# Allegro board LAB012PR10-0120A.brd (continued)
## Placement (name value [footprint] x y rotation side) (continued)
PC2  100P_0402_50V8J  [C_0402]  17.33 116.84 270 bottom
PC3  1000P_0402_50V7K  [C_0402]  17.33 113.77 90 bottom
PC4  100P_0402_50V8J  [C_0402]  16.31 113.77 90 bottom
PC5  0.1U_0402_25V6  [C_0402]  36.56 108.13 0 top
PC7  0.01U_0402_25V7K  [C_0402]  20.76 30.46 90 top
PC8  1000P_0402_50V7K  [C_0402]  19.49 30.46 90 top
PC13  .1U_0402_16V7K  [C_0402]  43.16 116.77 0 top
PC14  .1U_0402_16V7K  [C_0402]  81.39 51.44 0 bottom
PC15  0.01U_0402_25V7K  [C_0402]  84.64 49.34 270 bottom
PC16  .1U_0402_16V7K  [C_0402]  36.51 113.67 270 top
PC17  .1U_0402_16V7K  [C_0402]  38.36 117.28 180 top
PC100  4.7U_0603_6.3V6K  [C_0603]  75.22 9.29 180 top
PC101  220U_6.3V_M  [C_MP6VLPS220MC4R2]  70.65 27.86 90 bottom
PC102  100P_0402_50V8J  [C_0402]  76.35 20.11 180 top
PC103  680P_0603_50V8J  [C_0603]  67.67 25 270 top
PC104  0.22U_0603_25V7K  [C_0603]  73.15 21.52 90 top
PC105  1U_0603_25V6K  [C_0603]  70.33 18.83 270 bottom
PC106  4.7U_0603_10V6K  [C_0603]  68.23 17.86 270 bottom
PC107  220U_6.3V_M  [C_MP6VLPS220MC4R2]  71 8.36 270 bottom
PC108  100P_0402_50V8J  [C_0402]  75.42 16.82 0 bottom
PC109  4.7U_0603_10V6K  [C_0603]  75.49 18.1 0 top
PC110  0.22U_0603_25V7K  [C_0603]  71.77 12.98 90 top
PC111  680P_0603_50V8J  [C_0603]  67.49 13.83 90 top
PC112  10U_0805_25V6K  [C_0805]  63.04 19.41 0 bottom
PC113  0.1U_0402_25V7K  [C_0402]  62.85 18.44 0 top
PC114  2200P_0402_50V7K  [C_0402]  62.85 19.33 0 top
PC115  10U_0805_25V6K  [C_0805]  62.32 20.63 0 top
PC116  2200P_0402_50V7K  [C_0402]  62.85 18.11 0 bottom
PC117  0.1U_0402_25V7K  [C_0402]  62.85 17.25 0 bottom
PC200  0.1U_0603_25V7K  [C_0603]  88.89 13.01 180 bottom
PC201  2200P_0402_50V7K  [C_0402]  83.11 16.49 90 bottom
PC202  0.1U_0402_10V7K  [C_0402]  81.03 10.6 180 bottom
PC203  0.1U_0402_10V7K  [C_0402]  81.03 8.82 180 bottom
PC204  1U_0603_10V6K  [C_0603]  84.13 15.99 270 top
PC205  10U_0805_6.3V6K  [C_0805]  88.7 9.42 270 bottom
PC206  10U_0805_25V6K  [C_0805]  86.29 16.22 90 bottom
PC207  680P_0402_50V7K  [C_0402]  89.29 21.77 180 bottom
PC208  0.1U_0402_25V6  [C_0402]  82.23 16.49 90 bottom
PC209  1U_0603_10V6K  [C_0603]  82.86 14.6 90 top
PC210  0.033U_0402_16V7K  [C_0402]  84.13 8.26 270 bottom
PC211  10U_0805_6.3V6K  [C_0805]  87.27 7.93 180 bottom
PC212  10U_0805_25V6K  [C_0805]  84.51 16.22 90 bottom
PC213  330U_2.5V_M  [C_MP6VU330MC6]  99.37 10.98 180 bottom
PC214  220P_0402_25V8J  [C_0402]  81.9 7.42 0 top
PC300  0.22U_0402_10V6K  [C_0402]  182.99 44.89 0 bottom
PC301  680P_0603_50V7K  [C_0603]  173.92 47.24 90 bottom
PC302  0.1U_0603_25V7K  [C_0603]  183.76 53.01 180 bottom
PC303  2200P_0402_50V7K  [C_0402]  176.08 52.96 270 bottom
PC304  0.1U_0402_25V6  [C_0402]  175.19 52.96 270 bottom
PC305  10U_0805_25V6K  [C_0805]  178.49 52.93 90 bottom
PC306  10U_0805_25V6K  [C_0805]  173.79 52.98 270 bottom
PC307  330P_0402_50V7K  [C_0402]  183.88 48.44 0 bottom
PC308  47U_0805_6.3V6M  [C_0805]  182.43 38.96 90 top
PC309  47U_0805_6.3V6M  [C_0805]  180.52 38.96 90 top
PC310  22U_0805_6.3VAM  [C_0805]  176.97 38.96 90 top
PC311  22U_0805_6.3VAM  [C_0805]  178.75 38.96 90 top
PC312  4.7U_0603_6.3V6K  [C_0603]  182.37 50.47 0 bottom
PC313  4.7U_0603_6.3V6K  [C_0603]  179.83 53.01 0 bottom
PC400  1U_0402_6.3V6K  [C_0402]  210.11 8.63 0 top
PC401  4.7U_0603_10V6K  [C_0603]  208.71 6.85 0 top
PC402  0.1U_0402_16V7K  [C_0402]  210.11 11.74 0 top
PC403  0.01U_0402_25V7K  [C_0402]  200.84 11.93 0 top
PC404  22U_0805_6.3V6M  [C_0805]  201.3 8.28 90 top
PC500  1000P_0402_50V7K  [C_0402]  66.94 111.18 180 bottom
PC510  47P_0402_50V8J  [C_0402]  66.02 109.15 0 bottom
PC515  100U_25V_M  [C_EEEFZ1E101P]  66.86 114.86 90 bottom
PC516  100U_25V_M  [C_EEEFZ1E101P]  73.97 114.86 90 bottom
PC517  10U_0805_25V6K  [C_0805]  78.2 112.32 0 top
PC518  10U_0805_25V6K  [C_0805]  77.69 114.74 0 top
PC519  0.1U_0402_25V7K  [C_0402]  78.47 110.93 0 top
PC520  680P_0402_50V7K  [C_0402]  86.54 119.74 90 bottom
PC521  2200P_0402_25V7K  [C_0402]  78.47 110.93 0 bottom
PC522  82P_0402_50V8J  [C_0402]  68.38 105.29 270 top
PC523  4700P_0402_50V7K  [C_0402]  70.41 106.43 270 top
PC524  10U_0805_25V6K  [C_0805]  78.2 112.32 0 bottom
PC525  0.22U_0603_16V7K  [C_0603]  75.18 111.31 180 top
PC526  6800P_0402_25V7K  [C_0402]  66.94 107.12 180 bottom
PC527  330P_0402_50V7K  [C_0402]  67.42 103.43 0 bottom
PC528  0.1U_0603_25V7K  [C_0603]  73.78 109.35 0 bottom
PC529  0.1U_0402_10V6K  [C_0402]  75.49 105.59 180 top
PC530  .047U_0402_16V7K  [C_0402]  72.5 106.48 0 top
PC531  33P_0402_50V8J  [C_0402]  65.77 105.85 0 bottom
PC532  10U_0805_25V6K  [C_0805]  78.2 109.53 0 bottom
PC541  330P_0402_50V7K  [C_0402]  68.38 107.57 270 bottom
PC545  0.082U_0402_16V7K  [C_0402]  68.31 106.61 0 top
PC546  0.01U_0402_50V7K  [C_0402]  69.27 107.57 270 bottom
PC548  1U_0402_6.3V6K  [C_0402]  61.02 111.64 270 bottom
PC600  22U_0805_6.3VAM  [C_0805]  90.34 29.51 270 bottom
PC601  680P_0402_50V7K  [C_0402]  84.42 25.2 0 bottom
PC602  22U_0805_6.3VAM  [C_0805]  88.63 29.51 270 bottom
PC603  0.1U_0402_16V7K  [C_0402]  88.88 26.67 270 bottom
PC604  68P_0402_50V8J  [C_0402]  90.66 24.51 270 bottom
PC605  22U_0805_6.3VAM  [C_0805]  84.88 22.44 90 bottom
PC701  1000P_0402_50V7K  [C_0402]  46.86 7.28 0 bottom
PC702  0.022U_0402_25V7K  [C_0402]  26.97 40.95 180 bottom
PC703  10U_0805_25V6K  [C_0805]  37.23 33.2 180 top
PC704  10U_0805_25V6K  [C_0805]  37.23 35.11 180 top
PC705  2200P_0402_25V7K  [C_0402]  37.09 31.81 180 top
PC706  0.1U_0402_25V7K  [C_0402]  37.09 30.92 180 top
PC707  0.1U_0402_25V6  [C_0402]  47.94 18.27 90 bottom
PC708  0.1U_0402_25V6  [C_0402]  45.27 18.27 90 bottom
PC709  1U_0603_10V6K  [C_0603]  37.22 17.26 0 bottom
PC710  1U_0603_25V6K  [C_0603]  49.27 17.84 0 bottom
PC711  0.01UF_0402_25V7K  [C_0402]  50.81 14.53 180 bottom
PC712  10U_0805_25V6K  [C_0805]  24.91 16.06 180 bottom
PC713  10U_0805_25V6K  [C_0805]  24.91 17.84 180 bottom
PC714  10U_0805_25V6K  [C_0805]  27.11 29.05 90 top
PC715  680P_0402_50V7K  [C_0402]  41.2 31.35 90 bottom
PC716  10U_0805_25V6K  [C_0805]  24.91 19.61 180 bottom
PC717  0.047U_0402_25V7K  [C_0402]  47 17.33 180 bottom
PC718  10U_0805_25V6K  [C_0805]  30.1 29.1 90 top
PC719  1U_0603_10V6K  [C_0603]  37.24 18.48 0 bottom
PC720  1000P_0402_25V8J  [C_0402]  47.19 8.84 90 bottom
PC721  0.22U_0603_25V7K  [C_0603]  42.35 19.42 270 bottom
PC722  1U_0603_25V6K  [C_0603]  38.93 15.65 180 bottom
PC723  0.47U_0402_6.3V6K  [C_0402]  16.31 35.06 270 top
PC724  1000P_0402_25V8J  [C_0402]  18.9 23.42 0 bottom
PC725  1000P_0402_25V8J  [C_0402]  40.58 11.12 90 bottom
PC726  .1U_0402_16V7K  [C_0402]  44.48 8.87 90 bottom
PC727  220P_0402_50V8J  [C_0402]  49.56 8.77 90 bottom
PC728  2200P_0402_50V7K  [C_0402]  50.79 12.29 180 bottom
PC729  10U_0805_25V6K  [C_0805]  35.82 36.21 270 bottom
PC730  10U_0805_25V6K  [C_0805]  37.6 36.21 270 bottom
PC731  10U_0805_25V6K  [C_0805]  39.38 36.21 270 bottom
PC732  100U_25V_M  [C_EEEFZ1E101P]  46.79 23.42 90 bottom
PC733  5600P_0402_25V7K  [C_0402]  31.51 37.93 90 top
PC734  10U_0805_25V6K  [C_0805]  37.23 37.01 180 top
PC735  10U_0805_25V6K  [C_0805]  14.79 113.38 90 bottom
PC736  10U_0805_25V6K  [C_0805]  32.06 31.7 0 top
PC737  10U_0805_25V6K  [C_0805]  32.06 29.91 0 top
PC738  10U_0805_25V6K  [C_0805]  32.06 28.09 0 top
PC739  10U_0805_25V6K  [C_0805]  32.06 26.28 0 top
PC836  330U_D2_2V_Y  [C_D2]  57.97 63.71 270 top
PC837  330U_D2_2V_Y  [C_D2]  62.67 63.71 270 top
PC838  330U_D2_2V_Y  [C_D2]  67.37 63.71 270 top
PC839  330U_D2_2V_Y  [C_D2]  67.14 68.13 180 top
PC840  2.2U_0402_6.3V6M  [C_0402]  64.98 87.05 270 top
PC841  2.2U_0402_6.3V6M  [C_0402]  61.45 88.35 0 top
PC842  2.2U_0402_6.3V6M  [C_0402]  64.4 89.26 180 top
PC843  2.2U_0402_6.3V6M  [C_0402]  62.74 66.86 180 bottom
PC844  2.2U_0402_6.3V6M  [C_0402]  65.79 67.75 180 bottom
PC845  2.2U_0402_6.3V6M  [C_0402]  65.79 69.52 180 bottom
PC846  2.2U_0402_6.3V6M  [C_0402]  62.74 69.52 180 bottom
PC847  2.2U_0402_6.3V6M  [C_0402]  67.75 67.03 90 bottom
PC848  2.2U_0402_6.3V6M  [C_0402]  66.86 67.03 90 bottom
PC849  2.2U_0402_6.3V6M  [C_0402]  62.74 68.64 180 bottom
PC850  2.2U_0402_6.3V6M  [C_0402]  65.79 68.64 180 bottom
PC851  2.2U_0402_6.3V6M  [C_0402]  67.29 83.24 90 top
PC852  2.2U_0402_6.3V6M  [C_0402]  63.61 82.27 90 top
PC853  10U_0603_6.3V6M  [C_0603]  68.89 66.54 90 bottom
PC854  10U_0603_6.3V6M  [C_0603]  54.46 64.33 180 top
PC855  10U_0603_6.3V6M  [C_0603]  69.02 63.75 90 bottom
PC856  10U_0603_6.3V6M  [C_0603]  70.16 66.54 90 bottom
PC857  10U_0603_6.3V6M  [C_0603]  54.45 65.56 180 top
PC858  10U_0603_6.3V6M  [C_0603]  69.02 62.6 270 bottom
PC859  0.1U_0402_10V7K  [C_0402]  62.74 67.75 180 bottom
PC860  0.1U_0402_10V7K  [C_0402]  65.79 66.86 180 bottom
PC869  2.2U_0402_6.3V6M  [C_0402]  62.74 70.41 180 bottom
PC871  2.2U_0402_6.3V6M  [C_0402]  66.73 88.29 180 top
PC872  2.2U_0402_6.3V6M  [C_0402]  66.88 89.16 90 top
PC901  22U_0805_6.3V6M  [C_0805]  102.71 119.82 0 bottom
PC902  22U_0805_6.3V6M  [C_0805]  140.9 99.15 90 top
PC903  22U_0805_6.3V6M  [C_0805]  111.14 117.28 180 top
PC904  22U_0805_6.3V6M  [C_0805]  127.91 116.13 180 top
PC905  22U_0805_6.3V6M  [C_0805]  102.71 116.39 0 bottom
PC906  22U_0805_6.3V6M  [C_0805]  119.27 113.92 180 top
PC907  22U_0805_6.3V6M  [C_0805]  121.09 99.15 90 top
PC908  22U_0805_6.3V6M  [C_0805]  123.97 116.13 180 top
PC909  22U_0805_6.3V6M  [C_0805]  119.27 117.4 180 top
PC910  22U_0805_6.3V6M  [C_0805]  111.14 113.85 180 top
PC911  22U_0805_6.3V6M  [C_0805]  115.46 117.4 180 top
PC912  22U_0805_6.3V6M  [C_0805]  123.97 112.58 180 top
PC913  22U_0805_6.3V6M  [C_0805]  115.33 113.92 180 top
PC914  2.2U_0402_6.3V6M  [C_0402]  127.53 112.51 180 top
PC915  22U_0805_6.3V6M  [C_0805]  138.61 99.15 90 top
PC916  22U_0805_6.3V6M  [C_0805]  136.07 99.15 90 top
PC917  22U_0805_6.3V6M  [C_0805]  133.53 99.15 90 top
PC918  22U_0805_6.3V6M  [C_0805]  131.12 99.15 90 top
PC919  22U_0805_6.3V6M  [C_0805]  128.45 99.15 90 top
PC920  22U_0805_6.3V6M  [C_0805]  125.91 99.15 90 top
PC921  22U_0805_6.3V6M  [C_0805]  123.37 99.15 90 top
PC922  22U_0805_6.3V6M  [C_0805]  122.99 93.95 90 top
PC923  22U_0805_6.3V6M  [C_0805]  122.99 90.14 90 top
PC924  220U_D2_2.5VY_R9M  [C_D2]  127.79 95.18 0 top
PC1019  0.1U_0402_25V6K  [C_0402]  60.01 32.58 90 top
PC1020  1U_0603_10V6K  [C_0603]  61.21 39.17 180 top
PC1021  1U_0603_10V6K  [C_0603]  63.3 40.38 90 top
PC1022  1000P_0402_50V7K  [C_0402]  58.12 33.43 270 top
PC1023  10U_0805_25V6K  [C_0805]  57.84 45.22 90 top
PC1024  10U_0805_25V6K  [C_0805]  57.84 45.22 90 bottom
PC1025  2200P_0402_50V7K  [C_0402]  59.24 45.65 90 top
PC1026  0.22U_0603_25V7K  [C_0603]  59.49 43.17 270 bottom
PC1027  1000P_0402_50V7K  [C_0402]  57.16 39.55 180 top
PC1028  100P_0402_50V8J  [C_0402]  57.16 38.92 180 bottom
PC1029  680P_0603_50V7K  [C_0603]  56.24 46.22 90 bottom
PC1030  330P_0402_50V7K  [C_0402]  57.16 36.89 180 top
PC1031  0.01U_0402_50V7K  [C_0402]  57.16 35.87 180 bottom
PC1032  0.22U_0603_16V7K  [C_0603]  55.17 35.81 270 bottom
PC1033  390P_0402_50V7K  [C_0402]  54.08 39.43 0 bottom
PC1034  330P_0402_50V7K  [C_0402]  52.3 39.43 0 bottom
PC1035  0.1U_0603_50V7K  [C_0603]  56.38 35.12 0 top
PC1036  820P_0402_50V7K  [C_0402]  56.24 36.89 0 bottom
PC1040  0.01U_0402_50V7K  [C_0402]  58.02 38.66 0 top
PC1041  10U_0805_25V6K  [C_0805]  60.64 45.22 90 top
PC1042  0.1U_0402_25V6K  [C_0402]  59.24 45.65 90 bottom
PC1043  0.22U_0603_25V7K  [C_0603]  63.56 43.3 270 bottom
PC1044  680P_0603_50V7K  [C_0603]  74.34 48.34 270 top
PC1045  2200P_0402_50V7K  [C_0402]  62.03 45.65 90 bottom
PC1046  10U_0805_25V6K  [C_0805]  63.43 45.25 90 bottom
PC1047  0.1U_0402_25V6K  [C_0402]  62.03 45.65 90 top
PC1048  10U_0805_25V6K  [C_0805]  63.43 45.25 90 top
PC1049  10U_0805_25V6K  [C_0805]  60.64 45.22 90 bottom
PC1050  0.22U_0402_10V6K  [C_0402]  56.24 33.68 0 bottom
PC1051  0.22U_0402_10V6K  [C_0402]  56.24 34.98 0 bottom
PC1052  10U_0805_25V6K  [C_0805]  65.33 45.25 90 bottom
PC1100  0.1U_0402_25V6  [C_0402]  40.37 41.2 0 top
PC1101  2200P_0402_50V7K  [C_0402]  40.37 40.06 0 top
PC1102  10U_0805_25V6K  [C_0805]  39.97 42.6 0 top
PC1103  0.1U_0603_25V7K  [C_0603]  35.49 44.7 90 bottom
PC1104  0.1U_0402_16V7K  [C_0402]  30.59 41.97 0 bottom
PC1105  1U_0603_10V6K  [C_0603]  35.49 47.24 90 bottom
PC1106  680P_0402_50V7K  [C_0402]  40.95 51.39 270 top
PC1108  330U_2.5V_M  [C_MP6VU330MC6]  43.62 52.63 180 bottom
PC1300  22U_0805_6.3VAM  [C_0805]  74.48 63.17 270 top
PC1301  22U_0805_6.3VAM  [C_0805]  73.98 50.65 180 bottom
PC1302  0.1U_0402_10V7K  [C_0402]  74.1 52.38 180 top
PC1303  22U_0805_6.3VAM  [C_0805]  76.26 63.14 270 top
PC1304  680P_0402_50V7K  [C_0402]  76.38 54.92 180 top
PC1305  22U_0805_6.3VAM  [C_0805]  72.7 63.17 270 top
PC1306  22P_0402_50V8J  [C_0402]  77.27 53.27 270 top
PC1307  0.1U_0402_10V7K  [C_0402]  76.38 54.92 270 bottom
PC1308  22U_0805_6.3VAM  [C_0805]  70.92 63.17 270 top
PD1  -  [TVNST52302AB0_SOT523-3]  17.77 18.72 90 top
PD2  -  [TVNST52302AB0_SOT523-3]  19.17 22.92 270 top
PD101  -  [TVNST52302AB0_SOT523-3]  74.43 12.92 180 top
PD700  -  [BAS40CW_SOT323-3]  42.54 8.04 270 bottom
PH1  100K_0402_1%_TSM0B104F4251RZ  [R_0402]  128.66 91.11 180 top
PH500  470K_0402_5%_ TSM0B474J4702RE  [R_0402]  79.36 119.94 0 bottom
PH501  10KB_0402_5%_ERTJ0ER103J  [R_0402]  93.83 110.04 0 bottom
PH1002  470K_0402_5%_TSM0B474J4702RE  [R_0402]  50.56 44.56 270 top
PH1003  10K_0402_5%_ERTJ0ER103J  [R_0402]  50.73 62.08 90 bottom
PJP100  PAD-OPEN 4x4m  [JUMP_43X118]  75.5 20.77 0 bottom
PJP101  PAD-OPEN 4x4m  [JUMP_43X118]  76.09 13.77 0 bottom
PJP102  PAD-OPEN 4x4m  [JUMP_43X118]  75.5 26.04 0 bottom
PJP103  PAD-OPEN 4x4m  [JUMP_43X118]  76.09 8.56 0 bottom
PJP200  -  [JUMP_43X118]  98.69 25.2 0 bottom
PJP201  -  [JUMP_43X118]  98.69 31.17 0 bottom
PJP203  -  [JUMP_43X39]  90.68 7.98 90 bottom
PJP300  -  [JUMP_43X118]  174.94 37.05 270 top
PJP301  -  [JUMP_43X39]  181.11 54.79 180 bottom
PJP400  -  [JUMP_43X79]  206.13 5.47 90 top
PJP401  -  [JUMP_43X79]  202.32 6.57 270 top
PJP600  -  [JUMP_43X79]  81.66 23.74 0 bottom
PJP601  -  [JUMP_43X79]  89.64 31.22 90 bottom
PJP1100  -  [JUMP_43X118]  38.03 53.27 90 top
PJP1101  -  [JUMP_43X118]  44.13 53.27 90 top
PJP1300  -  [JUMP_43X79]  73.59 65.97 270 top
PJP1301  -  [JUMP_43X79]  77.46 51.64 0 bottom
PJPDC  ACES_50299-00501-003  [ACES_50299-00501-003_5P]  21.5 112.3 90 top
PL1  FBMJ4516HS720NT_2P  [TAIYO_FBMJ4516HS720NT_2P]  20.38 117.09 270 bottom
PL2  BLM15AG102SN1D_2P  [MURAT_BLM15AG102SN1D_2P]  20.38 105.29 90 top
PL3  FBMJ4516HS720NT_2P  [TAIYO_FBMJ4516HS720NT_2P]  22.73 25.84 180 top
PL4  FBMJ4516HS720NT_2P  [TAIYO_FBMJ4516HS720NT_2P]  25.71 112.65 270 top
PL5  FBMJ4516HS720NT_2P  [TAIYO_FBMJ4516HS720NT_2P]  22.73 28.63 180 top
PL6  2.2UH_PCMB053T-2R2MS_5.5A_20%  [CYNTE_PCMB053T-1R0MS_2P-S]  20.38 117.17 270 bottom
PL7  2.2UH_PCMB053T-2R2MS_5.5A_20%  [CYNTE_PCMB053T-1R0MS_2P-S]  25.71 112.72 270 top
PL100  2.2UH_PCMB063T-2R2MS_8A_20%  [PANAS_ETQP3W2R2WFN_2P]  63.56 22.25 270 bottom
PL101  2.2UH_PCMB063T-2R2MS_8A_20%  [PANAS_ETQP3W2R2WFN_2P]  63.94 14 90 bottom
PL102  1UH_PCMB053T-1R0MS_7A_20%  [L_5X5X3_M_2P]  56.29 18.06 0 bottom
PL200  1UH_PCMB063T-1R0MS_12A_20%  [PANAS_ETQP3W2R2WFN_2P]  99.5 18.22 0 bottom
PL201  FBMJ4516HS720NT_2P  [TAIYO_FBMJ4516HS720NT_2P]  79.74 20.7 270 bottom
PL301  0.68UH +-20% 7.9A 5X5X3 MOLDING  [L_5X5X3_M_2P]  179.13 45.67 270 bottom
PL302  FBMJ4516HS720NT_2P  [TAIYO_FBMJ4516HS720NT_2P]  171.76 47.74 90 bottom
PL501  FBMJ4516HS720NT_2P  [TAIYO_FBMJ4516HS720NT_2P]  61.57 117.02 180 bottom
PL502  0.15UH_PCMB104T-R15MSMS0R485_40A_20%  [TOKO_FDUE1040J-H-R36M-P3_4P]  87.05 116.01 0 bottom
PL503  2.2UH_PCMB053T-2R2MS_5.5A_20%  [CYNTE_PCMB053T-1R0MS_2P-S]  61.65 117.02 180 bottom
PL600  1UH_PH041H-1R0MS_3.8A_20%  [TAIYO_NRS4018T1R0NDGJ_2P]  85.45 27.74 90 bottom
PL701  2.2UH_PCMB104T-2R2MS_12A_20%  [CYNTE_PCMB104T-1R0MH_2P]  39.81 26.09 180 bottom
PL702  1UH_PCMB053T-1R0MS_7A_20%  [L_5X5X3_M_2P]  44.38 37.03 270 bottom
PL1000  FBMJ4516HS720NT_2P  [TAIYO_FBMJ4516HS720NT_2P]  72.83 43.69 270 top
PL1002  .36UH 20% PDME064T-R36MS1R405 24A  [PANAS_ETQP4LR15AFM_4P]  55.68 56.07 90 bottom
PL1003  .36UH 20% PDME064T-R36MS1R405 24A  [PANAS_ETQP4LR15AFM_4P]  64.32 56.07 90 bottom
PL1004  2.2UH_PCMB053T-2R2MS_5.5A_20%  [CYNTE_PCMB053T-1R0MS_2P-S]  72.83 43.76 270 top
PL1100  FBMJ4516HS720NT_2P  [TAIYO_FBMJ4516HS720NT_2P]  38.1 40.19 180 top
PL1101  1UH_PCMB063T-1R0MS_12A_20%  [PANAS_ETQP3W2R2WFN_2P]  38.18 45.52 180 bottom
PL1300  0.47UH_PCMB063T-R47MS_18A_20%  [PANAS_ETQP3W2R2WFN_2P]  73.34 58.37 270 bottom
PQ1  L2N7002DW1T1G_SC88-6  [2N7002DW-T-R7_SOT363-6]  34.83 107.36 90 top
PQ2  L2N7002DW1T1G_SC88-6  [2N7002DW-T-R7_SOT363-6]  34.83 112.31 90 top
PQ3  L2N7002DW1T1G_SC88-6  [2N7002DW-T-R7_SOT363-6]  85.76 52.01 270 bottom
PQ4  L2N7002DW1T1G_SC88-6  [2N7002DW-T-R7_SOT363-6]  39.71 117.67 270 top
PQ5  MMST3904-7-F_SOT323  [RHU002N06_SOT323-3]  22.41 101.31 180 top
PQ6  FDV301N_G 1N SOT23-3  [FDV301N_NL_SOT23-3]  22.92 105.49 180 top
PQ101  MDV1528URH-1N-PDFN33-8  [SIS412DN-T1-GE3_POWERPAK8-5]  61.86 25.04 180 top
PQ102  FDMC7692S-1N-MLP  [SIS412DN-T1-GE3_POWERPAK8-5]  64.2 22.17 0 top
PQ103  MDV1528URH-1N-PDFN33-8  [SIS412DN-T1-GE3_POWERPAK8-5]  59.71 13.59 0 top
PQ104  FDMC7692S-1N-MLP  [SIS412DN-T1-GE3_POWERPAK8-5]  65.48 16.46 180 top
PQ200  AON7408L  [SIS412DN-T1-GE3_POWERPAK8-5]  90.77 16.51 270 bottom
PQ201  AON7752  [SIS412DN-T1-GE3_POWERPAK8-5]  87.9 18.24 90 bottom
PQ501  CSD87351Q5D_SON8  [CSD86350Q5D_SON8]  79.4 114.81 90 bottom
PQ700  -  [AO4407AL_SO8]  25.58 38.54 270 bottom
PQ701  AO4423L_SO8  [AO4409L_SO8]  28.28 34.73 90 bottom
PQ702  -  [AO4407AL_SO8]  24.95 23 180 bottom
PQ703  -  [SIR472DP-T1-GE3_POWERPAK8-5]  39.3 31.42 0 top
PQ705  -  [SIRA06DP-T1-GE_POWERPAKSO-8-5]  35.61 29.39 270 top
PQ706  L2N7002DW1T1G_SC88-6  [2N7002DW-T-R7_SOT363-6]  14.41 36.63 0 top
PQ1003  -  [MDU1516URH_POWERDFN56-8-5]  55.9 47.45 180 top
PQ1004  MDU1511RH 1N POWERDFN56-8  [SIR472DP-T1-GE3_POWERPAK8-5]  57.87 49.14 90 top
PQ1005  -  [MDU1516URH_POWERDFN56-8-5]  69.14 48.83 180 top
PQ1006  MDU1511RH 1N POWERDFN56-8  [SIR472DP-T1-GE3_POWERPAK8-5]  63.3 54.41 270 top
PQ1007  MDU1511RH 1N POWERDFN56-8  [SIR472DP-T1-GE3_POWERPAK8-5]  57.87 52.95 270 bottom
PQ1008  MDU1511RH 1N POWERDFN56-8  [SIR472DP-T1-GE3_POWERPAK8-5]  63.3 49.33 90 bottom
PQ1100  AON7408L  [SIS412DN-T1-GE3_POWERPAK8-5]  38.51 45.41 180 top
PQ1101  AON7752  [SIS412DN-T1-GE3_POWERPAK8-5]  40.23 46.87 90 top
PR1  200K_0402_1%  [R_0402]  37.47 110.04 180 top
PR2  10K_0402_1%  [R_0402]  36.56 109.15 0 top
PR3  2.2K_0402_5%  [R_0402]  25.33 101.1 270 top
PR4  33_0402_5%  [R_0402]  25.33 103.38 270 top
PR5  3.3K_1206_5%  [R_1206]  30.22 110.55 0 top
PR6  100K_0402_1%  [R_0402]  20.58 101.27 180 top
PR7  1M_0402_1%  [R_0402]  31.12 108.64 180 top
PR8  10K_0402_1%  [R_0402]  24.31 100.18 90 top
PR9  15K_0402_1%  [R_0402]  19.67 100 0 top
PR10  1M_0402_1%  [R_0402]  30.21 107.37 0 top
PR11  0_0402_5%  [R_0402]  25.33 105.29 270 top
PR15  100_0402_5%  [R_0402]  20.55 19.23 0 top
PR16  10K_0402_1%  [R_0402]  21.47 18.34 180 top
PR18  100_0402_5%  [R_0402]  20.55 22.41 0 top
PR20  100_0402_5%  [R_0402]  20.55 23.42 0 top
PR23  150K_0402_1%  [R_0402]  44.08 114.99 180 top
PR24  12.1K_0402_1%  [R_0402]  82.35 48.75 90 bottom
PR25  12.1K_0402_1%  [R_0402]  81.46 48.75 90 bottom
PR26  115K_0402_1%  [R_0402]  43.16 115.88 0 top
PR27  392K_0402_1%  [R_0402]  43.16 117.66 0 top
PR28  10K_0402_1%  [R_0402]  37.39 112.75 90 top
PR29  100K_0402_1%  [R_0402]  36.56 111.82 0 top
PR30  160K_0402_1%  [R_0402]  85.55 48.42 90 bottom
PR31  1M_0402_1%  [R_0402]  31.12 112.45 180 top
PR32  100K_0402_1%  [R_0402]  82.3 50.55 180 bottom
PR33  1M_0402_1%  [R_0402]  30.21 113.47 0 top
PR34  115K_0402_1%  [R_0402]  38.36 118.17 180 top
PR35  499K_0402_1%  [R_0402]  37.45 115.37 0 top
PR36  392K_0402_1%  [R_0402]  38.36 116.39 180 top
PR37  10K_0402_1%  [R_0402]  80.09 52.33 0 bottom
PR100  0_0402_5%  [R0402_0OHM]  75.28 11.27 270 top
PR101  0_0402_5%  [R0402_0OHM]  73.5 11.27 270 top
PR102  10K_0402_5%  [R_0402]  74.39 11.27 270 top
PR103  2.2_0603_5%  [R_0603]  71.43 22.85 270 top
PR104  150K_0402_1%  [R_0402]  75.43 17 0 top
PR105  23.7K_0402_1%  [R_0402]  75.42 16.06 0 top
PR106  100K_0402_1%  [R_0402]  75.42 17.71 0 bottom
PR107  200K_0402_1%  [R_0402]  76.35 21 180 top
PR108  23.7K_0402_1%  [R_0402]  75.43 21.89 0 top
PR109  130K_0402_1%  [R_0402]  76.35 19.22 180 top
PR110  20K_0402_1%  [R_0402]  72.57 10.39 90 top
PR111  2.2_0603_5%  [R_0603]  70.52 14.38 270 top
PR112  4.7_1206_5%  [R_1206]  64.62 11.79 0 top
PR113  4.7_1206_5%  [R_1206]  64.81 26.78 0 top
PR114  200_0402_5%  [R_0402]  72.9 14.41 270 top
PR115  10K_0402_5%  [R_0402]  74.2 22.8 0 top
PR200  2.2_0603_5%  [R_0603]  88.96 11.93 270 bottom
PR201  0_0402_5%  [R0402_0OHM]  80.12 9.71 0 bottom
PR202  0_0402_5%  [R0402_0OHM]  80.12 7.93 0 bottom
PR203  4.7_1206_5%  [R_1206]  86.1 20.76 180 bottom
PR204  68.1K_0402_1%  [R_0402]  81.9 7.42 0 bottom
PR205  11.8K_0402_1%  [R_0402]  82.91 14.53 0 bottom
PR206  5.1_0603_5%  [R_0603]  80.83 12.56 90 bottom
PR207  54.9K_0402_1%  [R_0402]  81.9 8.31 0 bottom
PR208  680K_0402_1%  [R_0402]  80.12 11.49 0 bottom
PR209  0_0402_5%  [R0402_0OHM]  89.59 12.86 180 top
PR210  5.1_0603_5%  [R_0603]  80.74 12.35 180 top
PR300  0_0402_5%  [R0402_0OHM]  182.99 42.22 0 bottom
PR301  1M_0402_1%  [R_0402]  182.99 44 0 bottom
PR302  4.7_1206_5%  [R_1206]  174.3 43.43 90 bottom
PR303  0_0603_5%  [R0603_0OHM]  182.37 51.74 0 bottom
PR304  0_0402_5%  [R_0402]  183.9 47.55 180 bottom
PR305  15K_0402_1%  [R_0402]  182.94 48.49 90 bottom
PR306  0_0402_5%  [R_0402]  182.99 46.66 0 bottom
PR307  20K_0402_1%  [R_0402]  184.84 50.27 90 bottom
PR308  10K_0402_5%  [R_0402]  183.9 45.78 180 bottom
PR309  1K_0402_1%  [R_0402]  184.79 49.33 180 bottom
PR310  0_0402_5%  [R_0402]  182.99 43.11 0 bottom
PR400  1.58K_0402_1%  [R_0402]  200.84 12.82 0 top
PR401  1.74K_0402_1%  [R_0402]  201.76 11.04 180 top
PR402  10K_0402_5%  [R_0402]  211.03 12.76 180 top
PR403  10K_0402_5%  [R_0402]  210.11 10.85 0 top
PR500  130_0402_1%  [R_0402]  64.06 111.64 270 bottom
PR503  75_0402_5%  [R_0402]  63.05 111.64 270 bottom
PR504  54.9_0402_1%  [R_0402]  62.03 111.64 270 bottom
PR505  0_0402_5%  [R0402_0OHM]  64.06 110.72 90 top
PR506  0_0402_5%  [R0402_0OHM]  63.05 110.72 90 top
PR507  169K_0402_1%  [R_0402]  70.95 112.09 180 bottom
PR508  0_0402_5%  [R0402_0OHM]  62.03 110.72 90 top
PR510  0_0402_5%  [R0402_0OHM]  66.02 109.15 0 top
PR511  0_0402_5%  [R0402_0OHM]  66.02 111.18 0 top
PR512  124K_0402_1%  [R_0402]  73.77 108.13 0 top
PR519  1.5K_0402_5%  [R_0402]  66.02 110.16 0 top
PR521  97.6K_0402_1%  [R_0402]  66.02 110.16 0 bottom
PR525  3.83K_0402_1%  [R_0402]  66.02 108.13 0 top
PR528  27.4K_0402_1%  [R_0402]  66.02 108.13 0 bottom
PR533  0_0402_5%  [R_0402]  68.46 103.43 180 top
PR534  4.7_1206_5%  [R_1206]  84.26 120.2 180 bottom
PR535  210_0402_1%  [R_0402]  71.43 106.43 270 top
PR536  3.65K_0603_1%  [R_0603]  74.42 106.86 0 top
PR537  1.37K_0402_1%  [R_0402]  67.49 105.29 270 top
PR538  2.2_0603_5%  [R_0603]  75.18 109.4 180 top
PR539  909_0402_1%  [R_0402]  66.02 107.12 0 top
PR543  2K_0402_1%  [R_0402]  68.33 104.32 180 bottom
PR545  1.5K_0402_1%  [R_0402]  71.38 104.58 180 top
PR549  11K_0402_1%  [R_0402]  72.5 105.47 0 top
PR551  5.23K_0402_1%  [R_0402]  75.49 104.58 180 top
PR552  0_0402_5%  [R0402_0OHM]  74.02 110.42 0 bottom
PR558  4.99M_0402_1%  [R_0402]  73.41 106.48 180 bottom
PR601  0_0402_5%  [R0402_0OHM]  90.66 26.67 270 bottom
PR602  10K_0402_1%  [R_0402]  88.88 23.6 90 bottom
PR603  20K_0402_1%  [R_0402]  89.77 24.51 270 bottom
PR604  1M_0402_5%  [R_0402]  89.77 26.67 270 bottom
PR605  4.7_0603_5%  [R_0603]  85.32 26.28 180 bottom
PR701  3K_0402_1%  [R_0402]  44.94 7.29 0 bottom
PR702  0.02_1206_1%  [R_1206_4P-D]  35.53 38.03 0 bottom
PR704  10_0402_1%  [R_0402]  46.16 18.27 90 bottom
PR705  10_1206_5%  [R_1206]  50.79 16.06 180 bottom
PR706  0_0402_5%  [R_0402]  19.82 24.44 180 bottom
PR707  100K_0402_1%  [R_0402]  40.51 9.87 0 bottom
PR708  2.2_0402_1%  [R_0402]  39.91 15.37 90 bottom
PR709  2.2_0603_5%  [R_0603]  44.13 18.03 90 bottom
PR710  4.7_0603_5%  [R_0603]  39.72 17.17 90 bottom
PR711  51.1K_0402_1%  [R_0402]  50.81 13.64 180 bottom
PR712  158K_0402_1%  [R_0402]  42.26 9.87 0 bottom
PR713  499K_0402_1%  [R_0402]  14.41 40.64 270 top
PR714  0_0402_5%  [R0402_0OHM]  45.4 8.84 90 bottom
PR715  0_0402_5%  [R0402_0OHM]  46.3 8.84 90 bottom
PR716  0.02_1206_1%  [R_1206_4P-D]  27.31 22.17 270 bottom
PR717  10_0402_1%  [R_0402]  47.05 18.27 90 bottom
PR718  200K_0402_1%  [R_0402]  26.05 39.93 0 bottom
PR719  10K_0402_1%  [R_0402]  48.77 11.61 180 bottom
PR720  3.3K_1206_5%  [R_1206]  18.04 38.85 270 bottom
PR722  4.7_1206_5%  [R_1206]  39.87 32.82 180 bottom
PR723  232K_0402_1%  [R_0402]  47.86 14.46 0 bottom
PR724  499K_0402_1%  [R_0402]  17.46 34.14 90 top
PR725  150K_0402_1%  [R_0402]  28.07 34.47 180 top
PR726  27K_0402_1%  [R_0402]  48.28 9.73 270 bottom
PR727  1K_0402_1%  [R_0402]  48.77 13.39 180 bottom
PR728  9.09K_0402_1%  [R_0402]  48.77 12.5 180 bottom
PR1020  100K_0402_1%  [R_0402]  62.92 31.47 90 bottom
PR1022  0_0402_5%  [R0402_0OHM]  63.13 34.6 180 top
PR1024  1_0603_5%  [R_0603]  62.22 39.17 0 top
PR1025  0_0402_5%  [R_0402]  63.13 33.71 180 top
PR1027  0_0402_5%  [R0402_0OHM]  60.25 31.47 90 bottom
PR1029  133K_0402_1%  [R_0402]  57.19 33.43 270 top
PR1030  100K_0402_1%  [R_0402]  56.24 40.06 0 bottom
PR1031  27.4K_0402_1%  [R_0402]  56.29 33.42 270 top
PR1032  100K_0402_1%  [R_0402]  65.13 31.47 90 bottom
PR1033  100K_0402_1%  [R_0402]  64.24 31.47 90 bottom
PR1034  2.2_0603_1%  [R_0603]  57.84 41.77 90 bottom
PR1035  10K_0402_1%  [R_0402]  66.81 37.14 180 top
PR1036  4.7_1206_5%  [R_1206]  52.22 47.13 0 bottom
PR1037  301_0402_1%  [R_0402]  55.3 39.63 270 top
PR1038  32.4K_0402_1%  [R_0402]  55 40.31 180 bottom
PR1039  3.65K_0603_1%  [R_0603]  51.94 35.87 180 bottom
PR1040  825_0402_1%  [R_0402]  57.16 38.66 180 top
PR1041  137K_0402_1%  [R_0402]  55 38.54 180 bottom
PR1042  2.61K_0402_1%  [R_0402]  53.02 35.31 270 bottom
PR1043  1_0402_1%  [R_0402]  51.7 34.47 180 bottom
PR1044  11K_0402_1%  [R_0402]  53.9 35.31 270 bottom
PR1045  2K_0402_1%  [R_0402]  53.22 38.54 180 bottom
PR1046  590_0402_1%  [R_0402]  56.24 37.77 0 bottom
PR1047  10_0402_5%  [R_0402]  55.38 37.77 180 top
PR1048  100_0402_1%  [R_0402]  55.05 34.78 90 top
PR1049  0_0402_5%  [R0402_0OHM]  57.16 37.77 180 top
PR1050  0_0402_5%  [R0402_0OHM]  58.1 39.6 90 top
PR1051  10_0402_5%  [R_0402]  57.16 40.44 180 top
PR1052  13.3K_0402_1%  [R_0402]  57.03 31.47 90 bottom
PR1053  1_0402_1%  [R_0402]  53.85 34.47 180 top
PR1054  4.7_1206_5%  [R_1206]  72.6 49.83 270 top
PR1055  2.2_0603_1%  [R_0603]  65.21 41.9 90 bottom
PR1056  10K_0402_1%  [R_0402]  66.81 38.03 180 top
PR1057  3.65K_0603_1%  [R_0603]  51.94 35.87 180 top
PR1058  10K_0402_1%  [R_0402]  51.7 37.01 180 bottom
PR1059  10K_0402_1%  [R_0402]  51.7 34.47 180 top
PR1060  0_0402_5%  [R0402_0OHM]  50.48 47.98 90 top
PR1061  0_0402_5%  [R0402_0OHM]  60.08 54.54 180 top
PR1062  0_0402_5%  [R0402_0OHM]  63.76 48.42 90 top
PR1063  0_0402_5%  [R0402_0OHM]  62.41 48.44 90 top
PR1101  2.2_0603_5%  [R_0603]  34.16 43.49 0 bottom
PR1102  154K_0402_1%  [R_0402]  31.5 42.85 180 bottom
PR1103  0_0402_5%  [R0402_0OHM]  31.5 41.08 180 bottom
PR1104  4.7_1206_5%  [R_1206]  37.01 50.86 0 top
PR1105  470K_0402_1%  [R_0402]  31.04 49.08 0 bottom
PR1107  9.09K_0402_1%  [R_0402]  31.04 50.86 0 bottom
PR1108  10K_0402_1%  [R_0402]  31.04 49.97 0 bottom
PR1110  100K_0402_5%  [R_0402]  31.5 43.74 180 bottom
PR1300  200K_0402_5%  [R_0402]  77.15 55.94 180 bottom
PR1301  10K_0402_1%  [R_0402]  75.37 52.38 90 top
PR1302  5.9K_0402_1%  [R_0402]  76.26 53.27 270 top
PR1303  4.7_1206_5%  [R_1206]  75.62 58.86 270 top
PR1304  47K_0402_5%  [R_0402]  77.27 54.92 270 bottom
PU100  -  [TPS51285BRUKR_QFN20_3X3]  73.76 17.31 90 top
PU200  -  [RT8207MZQW_WQFN20_3X3]  84.8 9.68 180 bottom
PU300  -  [SY8206DQNC_QFN10_3X3]  180.6 48.46 90 bottom
PU400  -  [APL5930KAI-TRG_SO8]  203.33 12.31 270 top
PU501  -  [ISL95813HRZ-T_QFN20_3X4]  68.61 111.29 270 top
PU600  -  [SY8003DFC_DFN8_2X2]  87.85 23.91 180 bottom
PU701  ISL9520HRTZ-T_TQFN28_4X4~D  [ISL9520HRTZ-T_TQFN28_4X4]  46.15 15.1 270 bottom
PU1000  -  [ISL62771HRTZ-T_TQFN40_5X5]  63.32 34.14 180 bottom
PU1100  -  [TPS51212DSCR_SON10_3X3]  30.41 45.39 90 bottom
PU1300  SY8036LDBC_DFN10_3x3  [SY8036DBC_DFN10_3X3]  72.95 55.55 0 bottom
Q8  -  [2N7002K_SOT23-3]  172.78 5.8 180 top
Q2307  -  [2N7002K_SOT23-3]  168.84 5.8 180 top
Q2308  -  [2N7002K_SOT23-3]  162.49 5.8 180 top
Q2407  -  [MMST3904-7-F_SOT323-3]  93.81 31.36 0 bottom
Q2408  -  [MMST3904-7-F_SOT323-3]  110.86 81.4 0 bottom
Q2409  DII-DMN65D8LW-7~D  [SSM3K7002FU_SC70-3]  169.86 93.09 180 bottom
QA5  -  [DMN66D0LDW-7_SOT363-6]  190.67 21.58 0 top
QA6  -  [DMN66D0LDW-7_SOT363-6]  190.88 33.85 270 top
QC1  -  [DMN66D0LDW-7_SOT363-6]  171.06 82.24 270 top
QC2  -  [DMN66D0LDW-7_SOT363-6]  157.85 65.17 90 top
QC3  -  [2N7002K_SOT23-3]  154.92 100.6 180 top
QD2  -  [BSS138-G_SOT23-3]  139.35 55.05 270 top
QE4  2N7002KW 1N SOT323-3  [2N7002BKW_SOT323-3]  121.44 20.92 0 top
QE5  AP2606AGY-HF 1N SOT26-6  [SI3456BDV-T1-E3_TSOP6]  120.9 8.93 0 top
QE6  -  [DMN66D0LDW-7_SOT363-6]  25.27 64.68 90 bottom
QH1  -  [DMN66D0LDW-7_SOT363-6]  171.06 76.65 270 top
QM1  DII-DMN65D8LW-7~D  [SSM3K7002FU_SC70-3]  187.38 64.51 180 top
QS1  SSM3K7002FU_SC70-3~D  [SSM3K7002FU_SC70-3]  8.12 55.55 270 bottom
QV1  DMN66D0LDW-7 2N SOT363-6  [2N7002KDWH_SOT363-6]  68.13 99.62 90 bottom
QV2  -  [AO3413_SOT23-3]  45.14 108.11 180 bottom
QV3  -  [2N7002K_SOT23-3]  41.2 108.11 180 bottom
QV4  -  [2N7002K_SOT23-3]  49.08 108.11 180 bottom
QV8  -  [DMN66D0LDW-7_SOT363-6]  74.42 97.61 270 top
QX1  -  [2N7002KW_SOT323-3]  11.74 74.69 0 top
QX2  -  [SI3457CDV-T1-GE3_TSOP6]  5.2 74.4 0 top
QX3  -  [2N7002K_SOT23-3]  195.99 85.15 270 top
QX4  -  [DMN66D0LDW-7_SOT363-6]  195.4 77.84 180 top
QX5  -  [MMBT3904_NL_SOT23-3]  192.98 73.45 270 top
QX6  -  [DMN66D0LDW-7_SOT363-6]  8.55 103.25 0 top
R1  100_0402_1%  [R_0402]  112.63 100 0 top
R2  100_0402_1%  [R_0402]  111.51 101.27 180 top
R10  100K_0402_5%  [R_0402]  174.25 8.31 180 top
R16  100K_0402_5%  [R_0402]  171.3 8.31 0 top
R159  100K_0402_5%  [R_0402]  174.3 92.77 0 top
R245  0_0603_5%  [R_0603]  120.14 108.89 0 bottom
R248  0_0402_1%  [R0402_0OHM]  108.44 89.82 0 bottom
R250  0_0402_1%  [R0402_0OHM]  117.91 100.51 270 top
R251  0_0402_1%  [R0402_0OHM]  117.02 109.73 270 bottom
R252  75_0402_5%  [R_0402]  106.15 91.22 0 bottom
R253  150_0402_1%  [R_0402]  107.07 93.91 180 bottom
R254  43_0402_1%  [R_0402]  109.35 91.22 180 bottom
R255  10K_0402_5%  [R_0402]  108.44 93.91 0 bottom
R256  130_0402_1%  [R_0402]  106.15 92.49 0 bottom
R257  0_0402_1%  [R0402_0OHM]  109.35 92.49 180 bottom
R264  0_0603_1%  [R0603_0OHM]  145.85 71.24 90 top
R267  0_0805_1%  [R0805_0OHM]  136.33 90.44 270 top
R286  10K_0402_5%  [R_0402]  118.04 109.73 270 bottom
R416  0_0402_1%  [R0402_0OHM]  163.76 10.39 90 top
R2313  82K_0402_5%  [R_0402]  172.14 10.14 90 top
R2314  22_0603_5%  [R_0603]  168.52 7.65 0 top
R2315  470_0603_5%  [R_0603]  161.16 8.31 180 top
R2318  470K_0402_5%  [R_0402]  175.19 10.14 90 top
R2329  10K_0402_5%  [R_0402]  164.98 87.05 180 bottom
R2330  10K_0402_5%  [R_0402]  158.88 75.24 90 top
R2331  10K_0402_5%  [R_0402]  172.52 84.21 270 top
R2332  10K_0402_5%  [R_0402]  171.63 84.21 270 top
R2333  15_0402_1%  [R_0402]  181.67 25.76 90 top
R2334  1K_0402_1%  [R_0402]  183.27 23.35 180 top
R2335  1K_0402_1%  [R_0402]  177.73 23.88 270 top
R2336  22_0402_5%  [R_0402]  151.9 74.91 90 top
R2337  330K_0402_5%  [R_0402]  169.73 63.61 90 bottom
R2338  330K_0402_5%  [R_0402]  168.84 63.61 90 bottom
R2341  0_0402_5%  [R_0402]  109.86 95.81 180 top
R2346  1K_0402_5%  [R_0402]  116.82 105.97 0 bottom
R2347  220K_0402_5%~D  [R_0402]  142.88 51.49 180 top
R2348  66.5_0402_1%  [R_0402]  143.36 53.52 0 top
R2349  66.5_0402_1%  [R_0402]  143.36 54.41 0 top
R2350  66.5_0402_1%  [R_0402]  143.36 55.3 0 top
R2351  2M_0402_5%  [R_0402]  142.88 52.38 180 top
R2352  66.5_0402_1%  [R_0402]  143.36 56.19 0 top
R2354  0_0402_5%  [R_0402]  127.49 13.77 0 top
R2356  33_0402_5%  [R_0402]  197.03 14.61 270 top
R2357  33_0402_5%  [R_0402]  194.04 14.61 270 bottom
R2358  33_0402_5%  [R_0402]  193.17 13.77 180 bottom
R2359  33_0402_5%  [R_0402]  196.02 14.61 270 bottom
R2448  10K_0402_5%  [R_0402]  157.23 14.15 180 top
R2450  0_0402_5%  [R_0402]  154.69 14.15 180 top
R2451  470K_0402_5%  [R_0402]  166.3 10.39 90 top
R2452  0_0402_5%~D  [R_0402]  168.79 92.13 180 bottom
R2453  100K_0402_5%~D  [R_0402]  170.24 96.5 90 bottom
RA1  100K_0402_5%  [R_0402]  189.59 19.74 0 top
RA2  100K_0402_5%  [R_0402]  189.59 20.63 0 top
RA3  10K_0402_5%  [R_0402]  191.45 19.66 90 top
RA4  0_0402_5%  [R_0402]  192.33 19.66 90 top
RA5  470K_0402_5%  [R_0402]  193.73 34.04 270 top
RA6  10K_0402_5%  [R_0402]  193.17 14.66 180 bottom
RA7  10K_0402_5%  [R_0402]  188.78 32.36 90 top
RA8  0_0402_5%  [R_0402]  203.59 21.65 180 bottom
RA9  0_0402_5%  [R_0402]  200.34 23.85 90 bottom
RA10  0_0402_5%  [R_0402]  190.61 20.63 0 bottom
RA11  0_0402_5%  [R_0402]  190.61 21.57 0 bottom
RA12  100K_0402_5%  [R_0402]  195.23 25.01 270 top
RA13  100K_0402_5%  [R_0402]  191.04 17.57 90 bottom
RA19  10K_0402_5%  [R_0402]  189.67 14.74 270 top
RA29  0_0603_1%  [R0603_0OHM]  196.27 34.28 90 top
RA30  0_0603_1%  [R0603_0OHM]  187.83 25.71 180 top
RA31  0_0603_1%  [R0603_0OHM]  201.59 24.24 180 top
RA32  0_0603_1%  [R0603_0OHM]  187.75 23.54 225 top
RA53  2.2K_0402_5%  [R_0402]  189.74 33.33 180 bottom
RA55  8.2_0402_1%  [R_0402]  196.86 24.74 90 bottom
RA56  8.2_0402_1%  [R_0402]  197.75 24.74 90 bottom
RA79  1K_0402_1%  [R_0402]  190.56 13.82 90 top
RA80  1K_0402_1%  [R_0402]  188.78 29.85 270 top
RA81  10K_0402_5%  [R_0402]  192.33 14.74 270 top
RA82  1K_0402_1%  [R_0402]  188.78 27.16 90 top
RA83  10K_0402_5%  [R_0402]  191.12 30.28 0 bottom
RA84  10K_0402_5%  [R_0402]  191.12 26.22 0 bottom
RA130  22_0402_5%  [R_0402]  195 13.69 90 bottom
RA165  4.7K_0402_5%  [R_0402]  188.83 29.27 0 bottom
RA166  4.7K_0402_5%  [R_0402]  188.83 27.23 0 bottom
RA1109  2.2K_0402_5%  [R_0402]  189.74 30.79 180 bottom
RA1110  0_0603_1%  [R0603_0OHM]  197.99 19.49 0 top
RA1111  0_0603_1%  [R0603_0OHM]  194.78 21.28 90 top
RA1112  0_0402_5%  [R_0402]  197.03 14.61 270 bottom
RA1113  0_0402_5%  [R_0402]  198.81 13.06 90 bottom
RC1  330K_0402_1%  [R_0402]  174.89 66.98 180 top
RC2  330K_0402_1%  [R_0402]  173.92 65.92 270 top
RC3  1K_0402_5%  [R_0402]  197.87 12.25 180 top
RC4  10M_0402_5%  [R_0402]  174.55 73.41 270 top
RC5  20K_0402_5%  [R_0402]  150.74 71.25 270 top
RC6  20K_0402_5%  [R_0402]  149.68 71.25 270 top
RC7  1M_0402_5%  [R_0402]  174.89 69.78 180 top
RC8  1K_0402_5%  [R_0402]  194.42 12.76 0 top
RC9  100K_0402_5%  [R_0402]  167.75 88.45 0 bottom
RC10  1K_0402_5%  [R_0402]  177.48 65.41 270 top
RC11  10K_0402_5%  [R_0402]  160 92.92 0 bottom
RC12  1M_0402_5%  [R_0402]  136.15 108.01 180 bottom
RC13  3.01K_0402_1%  [R_0402]  146.49 109.22 270 bottom
RC14  1.82K_0402_1%  [R_0402]  119.31 64.65 270 top
RC15  1.82K_0402_1%  [R_0402]  116.47 64.7 180 top
RC16  1.82K_0402_1%  [R_0402]  116.47 63.68 180 top
RC17  2.2_0402_1%  [R_0402]  119.26 62.67 180 top
RC18  2.2_0402_1%  [R_0402]  114.69 65.71 180 top
RC19  2.2_0402_1%  [R_0402]  115.55 62.67 0 top
RC20  1.82K_0402_1%  [R_0402]  120.12 62.67 0 top
RC21  1.82K_0402_1%  [R_0402]  115.55 65.71 0 top
RC22  1.82K_0402_1%  [R_0402]  114.69 62.67 180 top
RC23  24.9_0402_1%~D  [R_0402]  120.12 61.65 0 top
RC24  24.9_0402_1%~D  [R_0402]  115.55 66.73 0 top
RC25  24.9_0402_1%~D  [R_0402]  114.69 61.65 180 top
RC26  0_0402_1%  [R0402_0OHM]  160.92 89.34 180 bottom
RC27  10K_0402_5%  [R_0402]  157.66 71.51 270 top
RC28  10K_0402_5%  [R_0402]  158.68 71.51 270 top
RC29  10K_0402_5%  [R_0402]  154.88 75.24 90 top
RC31  8.2K_0402_5%  [R_0402]  157.1 75.24 90 top
RC32  10K_0402_5%  [R_0402]  155.12 71.1 90 top
RC33  0_0402_5%  [R_0402]  152.84 72.11 90 top
RC34  1K_0402_5%  [R_0402]  157.66 73.79 270 top
RC35  0_0402_5%  [R_0402]  159.95 68.56 90 top
RC36  8.2K_0402_5%  [R_0402]  160.92 91.75 180 top
RC37  0_0402_1%  [R0402_0OHM]  159.7 70.59 90 top
RC38  0_0402_1%  [R0402_0OHM]  156.67 85.15 180 top
RC39  10K_0402_5%  [R_0402]  155.76 75.24 90 top
RC41  0_0402_1%  [R0402_0OHM]  153.85 72.11 90 top
RC42  0_0402_1%  [R0402_0OHM]  158.68 69.47 270 top
RC43  0_0402_1%  [R0402_0OHM]  92.46 86.8 180 top
RC44  0_0402_1%  [R0402_0OHM]  94.24 88.96 180 top
RC45  0_0402_1%  [R0402_0OHM]  92.46 88.96 180 top
RC46  0_0402_1%  [R0402_0OHM]  84.44 89.46 0 top
RC48  1K_0402_5%  [R_0402]  96.15 73.44 180 top
RC49  0_0402_5%  [R_0402]  96.15 74.32 180 top
RC50  0_0402_5%  [R_0402]  94.62 76.51 180 top
RC51  1K_0402_5%  [R_0402]  82.66 78.16 0 top
RC52  0_0402_5%  [R_0402]  94.62 79.56 180 top
RC56  1K_0402_5%  [R_0402]  94.62 69.78 180 top
RC57  0_0402_1%  [R0402_0OHM]  109.86 96.83 180 top
RC58  49.9_0402_1%  [R_0402]  108.95 94.8 0 top
RC59  0_0402_1%  [R0402_0OHM]  109.35 87.18 180 bottom
RC60  62_0402_5%  [R_0402]  109.86 98.86 180 top
RC62  0_0402_5%  [R_0402]  108.44 88.07 0 bottom
RC63  0_0402_5%  [R_0402]  91.55 87.94 0 top
RC64  1K_0402_5%  [R_0402]  93.71 78.54 0 top
RC65  0_0402_5%  [R_0402]  107.32 87.18 180 bottom
RC66  10K_0402_5%  [R_0402]  119.51 105.97 180 bottom
RC67  56_0402_5%  [R_0402]  108.95 97.85 0 top
RC68  200_0402_1%  [R_0402]  114.99 72.27 270 top
RC69  120_0402_1%  [R_0402]  116.01 72.27 270 top
RC70  100_0402_1%  [R_0402]  113.98 72.27 270 top
RC71  24.9_0402_1%~D  [R_0402]  145.47 100.51 180 top
RC72  0_0402_5%  [R_0402]  156.37 111.64 90 top
RC73  10K_0402_5%  [R_0402]  160.92 94.92 180 top
RC74  10K_0402_5%  [R_0402]  160.92 93.65 180 top
RC75  10K_0402_5%  [R_0402]  158.3 111.61 90 top
RC76  10K_0402_5%  [R_0402]  160.92 95.65 180 bottom
RC77  10K_0402_5%  [R_0402]  160.92 95.81 180 top
RC78  10K_0402_5%  [R_0402]  28.37 59.53 90 bottom
RC79  10K_0402_5%  [R_0402]  160.92 94.76 180 bottom
RC81  0_0402_1%  [R0402_0OHM]  157.28 111.61 90 top
RC82  0_0402_1%  [R0402_0OHM]  161.73 113.44 270 bottom
RC84  100K_0402_5%  [R_0402]  159.44 112.53 270 top
RC87  100K_0402_5%  [R_0402]  154.06 108.79 270 bottom
RC88  1K_0402_1%  [R_0402]  166.6 100.51 0 bottom
RC89  100K_0402_5%  [R_0402]  162.6 112.53 90 bottom
RC90  22.6_0402_1%~D  [R_0402]  149.66 75.57 270 top
RC91  3.01K_0402_1%  [R_0402]  139.17 105.08 0 bottom
RC97  0_0402_5%  [R_0402]  158.62 73.8 270 top
RC98  100K_0402_5%  [R_0402]  166.6 95.56 0 bottom
RC99  10K_0402_5%  [R_0402]  166.6 97.34 0 bottom
RC100  10K_0402_5%  [R_0402]  167.52 96.45 180 bottom
RC101  49.9_0402_1%  [R_0402]  148.65 73.41 270 top
RC102  10K_0402_5%  [R_0402]  160.92 92.77 180 top
RC103  10K_0402_5%  [R_0402]  167.75 87.56 0 bottom
RC104  10K_0402_5%  [R_0402]  164.06 87.94 0 bottom
RC105  10K_0402_5%  [R_0402]  155.96 86.16 180 top
RC106  10K_0402_5%  [R_0402]  160.92 98.3 180 bottom
RC107  10K_0402_5%  [R_0402]  160 91.99 0 bottom
RC108  100K_0402_5%  [R_0402]  160.92 97.43 180 bottom
RC109  10K_0402_5%  [R_0402]  164.98 97.29 180 bottom
RC110  10K_0402_5%  [R_0402]  167.75 86.67 0 bottom
RC111  100K_0402_5%  [R_0402]  160.92 96.54 180 bottom
RC112  10K_0402_5%  [R_0402]  167.52 93.78 180 bottom
RC113  10K_0402_5%  [R_0402]  166.6 94.67 0 bottom
RC114  10K_0402_5%  [R_0402]  164.98 96.42 180 bottom
RC115  100K_0402_5%  [R_0402]  160.92 99.18 180 bottom
RC116  10K_0402_5%  [R_0402]  160 93.81 0 bottom
RC118  1K_0402_5%  [R_0402]  160.66 102.29 180 bottom
RC119  10K_0402_5%  [R_0402]  175.27 96.7 180 top
RC120  1K_0402_5%  [R_0402]  172.22 89.84 180 top
RC121  1K_0402_5%  [R_0402]  160.92 91.11 180 bottom
RC122  1K_0402_5%  [R_0402]  159.75 103.18 0 bottom
RC123  1K_0402_5%  [R_0402]  174.35 97.72 0 top
RC124  10K_0402_5%  [R_0402]  172.22 87.94 180 top
RC125  10K_0402_5%  [R_0402]  157.99 75.24 90 top
RC126  0_0603_1%  [R0603_0OHM]  148.01 108.2 90 bottom
RC127  0_0402_5%  [R_0402]  159.95 90.56 270 top
RC128  0_0402_5%  [R_0402]  160.84 90.56 270 top
RC129  0_0402_5%  [R_0402]  160 88.7 0 top
RC130  1K_0402_1%  [R_0402]  105.01 88.24 180 bottom
RC131  3.01K_0402_1%  [R_0402]  149.28 108.44 90 bottom
RC132  49.9_0402_1%  [R_0402]  116.82 92.89 0 top
RC133  8.2K_0402_1%  [R_0402]  148.01 106.68 270 bottom
RC134  49.9_0402_1%  [R_0402]  148.65 75.57 270 top
RC135  51_0402_1%  [R_0402]  105.04 87.18 180 bottom
RC136  0_0402_5%  [R_0402]  174.99 86.42 0 top
RC137  0_0402_5%  [R_0402]  175.24 82.73 0 top
RC138  1K_0402_1%  [R_0402]  117.23 89.84 180 top
RC139  0_0402_5%  [R_0402]  83.57 74.99 180 top
RC140  0_0402_5%  [R_0402]  83.57 75.87 180 top
RC141  0_0402_1%  [R0402_0OHM]  109.86 93.78 180 top
RC142  0_0402_5%  [R_0402]  149.21 96.19 0 top
RC143  0_0402_5%  [R_0402]  143.36 70.67 0 top
RC163  100_0402_1%  [R_0402]  113.54 101.27 180 top
RC362  1K_0402_1%  [R_0402]  82.66 80.19 0 top
RC363  0_0402_5%  [R_0402]  170.03 96.58 0 top
RC364  0_0402_5%  [R_0402]  170.03 97.85 0 top
RC365  0_0402_1%  [R0402_0OHM]  172.73 96.58 180 top
RC366  0_0402_1%  [R0402_0OHM]  172.73 97.85 180 top
RC367  0_0402_5%  [R_0402]  153.41 101.41 180 top
RC368  100K_0402_5%  [R_0402]  156.71 63.94 0 top
RD1  0_0402_1%  [R0402_0OHM]  98.23 51.19 270 top
RD3  470_0402_5%  [R_0402]  102.8 39.35 90 top
RD4  0_0402_1%  [R0402_0OHM]  139.38 38.97 90 top
RD5  0_0402_1%  [R0402_0OHM]  103.82 39.35 90 top
RD6  10K_0402_5%  [R_0402]  157.41 47.22 90 top
RD7  10K_0402_5%  [R_0402]  158.43 48.14 270 top
RD8  0_0402_1%  [R0402_0OHM]  107.12 39.88 270 top
RD10  0_0402_1%  [R0402_0OHM]  151.44 26.01 90 top
RD12  10K_0402_5%  [R_0402]  170.87 35.79 0 top
RD13  10K_0402_5%  [R_0402]  170.87 34.9 0 top
RE1  10K_0402_5%  [R_0402]  131.12 22.61 270 top
RE2  10K_0402_5%  [R_0402]  144.5 22.4 270 top
RE3  100K_0402_1%  [R_0402]  151.57 5.29 90 top
RE5  100K_0402_1%  [R_0402]  150.68 6.2 270 top
RE7  0_0402_5%  [R_0402]  150.12 1.96 180 top
RE8  47K_0402_5%  [R_0402]  126.8 2.14 90 top
RE9  4.7K_0402_5%  [R_0402]  151.44 16.26 270 top
RE10  4.7K_0402_5%  [R_0402]  150.5 16.31 180 top
RE12  0_0402_5%  [R_0402]  136.07 21.7 90 top
RE18  10K_0402_5%  [R_0402]  126.75 5.39 180 top
RE36  43_0402_1%  [R_0402]  141.15 22.61 270 top
RE37  0_0402_1%  [R0402_0OHM]  132.14 22.61 270 top
RE43  43_0402_1%  [R_0402]  137.09 21.7 90 top
RE44  0_0402_1%  [R0402_0OHM]  109.45 21.87 90 top
RE47  100K_0402_5%  [R_0402]  142.61 22.65 270 top
RE49  100K_0402_5%  [R_0402]  171.1 121.37 270 bottom
RE50  10K_0402_5%  [R_0402]  2.52 73.97 0 top
RE58  100K_0402_5%  [R_0402]  120.86 18.06 0 top
RE59  0_0805_5%  [R_0805]  115.5 23.64 270 top
RE60  240_0402_1%  [R_0402]  95.95 46.07 270 top
RE68  10K_0402_5%  [R_0402]  121.82 21.9 180 top
RE71  10K_0402_5%  [R_0402]  138.99 22.61 270 top
RE72  10K_0402_5%  [R_0402]  149.59 18.98 0 top
RE73  10K_0402_5%  [R_0402]  143.51 22.4 270 top
RE326  1K_0402_5%  [R_0402]  145.41 21.48 90 top
RE327  0_0603_1%  [R0603_0OHM]  125.66 3.55 270 top
RE328  0_0603_5%  [R_0603]  139.36 24.13 180 top
RE329  100K_0402_5%  [R_0402]  22.59 62.56 0 top
RE330  0_0603_5%  [R_0603]  10.85 70.48 270 top
RE331  0_0603_5%  [R_0603]  12.12 70.48 270 top
RE332  13.7K_0402_1%  [R_0402]  12.58 63.75 90 bottom
RE333  13.7K_0402_1%  [R_0402]  14.42 63.75 90 bottom
RE334  10K_0402_5%  [R_0402]  25.58 62.72 90 bottom
RE335  10K_0402_5%  [R_0402]  26.85 62.72 90 bottom
RE336  0_0402_1%  [R0402_0OHM]  27.74 62.72 90 bottom
RE337  0_0402_1%  [R0402_0OHM]  24.69 62.72 90 bottom
RE338  0_0402_5%  [R_0402]  25.25 62.59 180 top
RE339  10K_0402_5%  [R_0402]  19.91 62.23 180 top
RE340  10K_0402_5%  [R_0402]  26.07 62.58 0 top
RG1  330_0402_5%  [R_0402]  181.25 81.72 90 top
RG2  0_0402_5%  [R_0402]  182.24 78.67 90 top
RG3  0_0402_5%  [R_0402]  176.08 76.2 270 top
RG4  330_0402_5%  [R_0402]  182.12 81.72 90 top
RG5  33_0402_5%  [R_0402]  189.08 80.95 0 top
RG6  22_0402_5%  [R_0402]  132.54 111.69 180 top
RG8  0_0402_5%  [R_0402]  177.26 107.5 180 top
RL1  0_0603_5%  [MURAT_BLM18AG601SN1D_L0603_2P]  170.43 107.12 0 top
RL6  0_0603_5%  [R0603_0OHM]  170.05 105.21 0 bottom
RL19  75_0603_5%  [R_0603]  189.92 104.58 180 top
RL20  75_0603_5%  [R_0603]  190.01 107.78 180 top
RL27  100K_0402_5%  [R_0402]  165.54 111.87 90 bottom
RL31  2.49K_0402_1%  [R_0402]  176.59 104.88 90 top
RL33  1K_0402_5%  [R_0402]  171.05 101.27 0 top
RL34  10K_0402_5%  [R_0402]  170.41 104.07 0 bottom
RL35  15K_0402_5%  [R_0402]  171.05 102.16 0 top
RL37  10K_0402_5%  [R_0402]  179.01 100.86 0 bottom
RL38  10K_0402_5%  [R_0402]  166.43 112.78 270 bottom
RL39  10K_0402_5%  [R_0402]  173.46 105.8 0 top
RL40  10K_0402_5%  [R_0402]  187.51 93.58 90 bottom
RM5  0_0402_1%  [R0402_0OHM]  184.71 65.79 270 top
RM6  0_0402_1%  [R0402_0OHM]  185.6 65.79 270 top
RM7  0_1206_5%  [R_1206]  194.11 62.22 90 top
RM8  10K_0402_5%~D  [R_0402]  187.46 65.71 180 top
RM9  100K_0402_5%  [R_0402]  128.02 6.91 180 top
RM10  10K_0402_5%  [R_0402]  197.49 77.92 180 bottom
RP34  10K_8P4R_5%  [RP_0804_8P4R]  59.38 102.36 270 bottom
RP36  2.2K_0804_8P4R_5%  [RP_0804_8P4R]  149.98 11.02 0 top
RP37  10K_8P4R_5%  [RP_0804_8P4R]  163.82 89.02 0 bottom
RP39  15_8P4R_5%  [RP_0804_8P4R]  180.51 25.65 270 top
RP40  2.2K_0804_8P4R_5%  [RP_0804_8P4R]  171.44 79.54 0 top
RP41  10K_8P4R_5%  [RP_0804_8P4R]  128.06 108.45 90 bottom
RP42  10K_8P4R_5%  [RP_0804_8P4R]  168.91 91.05 180 bottom
RP44  51_8P4R_5%  [RP_0804_8P4R]  113.28 97.22 180 top
RP45  51_8P4R_5%  [RP_0804_8P4R]  113.28 94.43 180 top
RP46  0_8P4R_5%  [RP_0804_8P4R]  95.25 80.71 180 top
RP48  51_8P4R_5%  [RP_0804_8P4R]  110.48 89.3 0 top
RP49  1K_0804_8P4R_5%  [RP_0804_8P4R]  171.44 86.78 0 top
RP50  0_8P4R_5%  [RP_0804_8P4R]  169.03 98.75 0 bottom
RP51  100K_8P4R_5%  [RP_0804_8P4R]  155.87 112.26 90 bottom
RP52  2.2K_8P4R_5%  [RP_0804_8P4R]  153.08 112.26 90 bottom
RP53  2.2K_0804_8P4R_5%  [RP_0804_8P4R]  163.82 98.37 0 bottom
RP54  8.2K_8P4R_5%  [RP_0804_8P4R]  163.82 91.81 0 bottom
RP55  10K_8P4R_5%  [RP_0804_8P4R]  161.46 75.81 270 top
RP58  680_8P4R_5%  [RP_0804_8P4R]  195.96 87.95 180 top
RP59  680_8P4R_5%  [RP_0804_8P4R]  195.96 80.84 180 top
RS8  0_0402_5%  [R_0402]  185.32 15.06 0 bottom
RS18  0_0402_5%  [R_0402]  183.58 8.26 270 top
RS19  0_0402_5%  [R_0402]  185.1 16.39 270 top
RS20  0_0402_5%  [R_0402]  185.35 7.34 90 top
RS21  0_0402_5%  [R_0402]  184.21 15.47 90 top
RS22  0_0402_5%  [R_0402]  184.47 7.34 90 top
RS23  0_0402_5%  [R_0402]  187.13 8.26 270 top
RS24  2K_0402_5%  [R_0402]  183.32 15.47 90 top
RS25  0_0402_5%  [R_0402]  183.24 15.55 0 bottom
RS26  0_0402_5%  [R_0402]  188.91 7.34 90 top
RS27  0_0402_5%  [R_0402]  181.46 15.55 0 top
RS28  0_0402_5%  [R_0402]  186.24 15.96 180 bottom
RS29  0_0402_5%  [R_0402]  182.71 7.33 90 top
RS30  0_0402_5%  [R_0402]  186.24 7.34 90 top
RS31  5.1K_0402_1%  [R_0402]  188.02 8.26 270 top
RS32  100K_0402_5%~D  [R_0402]  10.85 55.63 270 bottom
RS33  4.7K_0402_5%  [R_0402]  186.87 16.39 270 top
RS34  4.7K_0402_5%  [R_0402]  181.79 8.26 270 top
RS35  4.7K_0402_5%  [R_0402]  185.98 15.47 90 top
RS36  4.7K_0402_5%  [R_0402]  180.9 8.26 270 top
RS37  0_0402_5%  [R_0402]  178.22 9.15 180 top
RS38  0_0402_5%  [R_0402]  178.22 7.34 90 top
RV1  1.69K_0402_1%  [R_0402]  66.99 78.11 270 top
RV2  1K_0402_1%  [R_0402]  61.91 98.3 270 top
RV3  1K_0402_1%  [R_0402]  68 78.11 270 top
RV4  100K_0402_5%  [R_0402]  75.88 76.43 90 top
RV5  45.3K_0402_1%  [R_0402]  70.24 98.48 180 bottom
RV6  45.3K_0402_1%  [R_0402]  67.37 98.48 0 bottom
RV8  8.45K_0402_1%  [R_0402]  79.76 83.49 180 top
RV9  2K_0402_1%  [R_0402]  76.56 84.76 0 top
RV11  8.45K_0402_1%  [R_0402]  79.76 81.21 180 top
RV12  4.75K_0402_1%  [R_0402]  76.56 81.21 0 top
RV13  4.75K_0402_1%  [R_0402]  76.56 87.05 0 top
RV15  8.45K_0402_1%  [R_0402]  79.76 79.05 180 top
RV16  2K_0402_1%  [R_0402]  76.56 79.05 0 top
RV17  1K_0402_1%  [R_0402]  59.87 101.73 270 top
RV20  1M_0402_5%  [R_0402]  79.56 73.16 270 bottom
RV21  10K_0402_5%  [R_0402]  64.45 101.73 270 bottom
RV22  51K_0402_5%  [R_0402]  39.86 106.23 0 bottom
RV23  10K_0402_5%  [R_0402]  41.89 106.23 0 bottom
RV24  470_0603_5%  [R_0603]  48.13 106.23 0 bottom
RV25  270K_0402_5%  [R_0402]  41.79 112.83 180 bottom
RV26  10K_0402_5%  [R_0402]  45.6 112.83 180 bottom
RV27  0_0603_1%  [R0603_0OHM]  76.07 88.19 180 top
RV28  8.45K_0402_1%  [R_0402]  79.89 85.78 180 top
RV29  10K_0402_5%  [R_0402]  71.11 77.06 90 top
RV30  0_0603_1%  [R0603_0OHM]  73.78 70.29 0 top
RV31  0_0805_1%  [R0805_0OHM]  65.63 71.35 0 top
RV32  40.2_0402_1%  [R_0402]  55.43 70.46 90 top
RV33  40.2_0402_1%  [R_0402]  55.43 69.09 270 top
RV34  100_0402_1%  [R_0402]  57.33 68.18 90 top
RV35  100_0402_1%  [R_0402]  56.32 71.38 270 top
RV36  49.9_0402_1%  [R_0402]  65.13 96.96 0 top
RV37  10_0402_1%  [R_0402]  65.13 95.94 0 top
RV38  5.1K_0402_1%  [R_0402]  65.13 94.92 0 top
RV39  120_0402_1%  [R_0402]  60 73.26 90 top
RV40  51.1_0402_1%  [R_0402]  63.73 98.3 270 top
RV41  51.1_0402_1%  [R_0402]  62.79 98.3 270 top
RV42  4.99K_0402_1%  [R_0402]  36.63 68.05 90 bottom
RV43  4.99K_0402_1%  [R_0402]  37.52 82.68 270 bottom
RV44  4.99K_0402_1%  [R_0402]  35.74 68.97 270 bottom
RV45  4.99K_0402_1%  [R_0402]  39.55 81.77 90 bottom
RV46  243_0402_1%  [R_0402]  36.63 81.77 90 bottom
RV47  243_0402_1%  [R_0402]  33.97 68.97 270 bottom
RV48  40.2_0402_1%  [R_0402]  38.41 68.97 270 bottom
RV49  40.2_0402_1%  [R_0402]  37.52 68.97 270 bottom
RV50  4.99K_0402_1%  [R_0402]  37.39 87.86 90 bottom
RV51  4.99K_0402_1%  [R_0402]  34.47 102.37 270 top
RV52  4.99K_0402_1%  [R_0402]  38.28 88.78 270 bottom
RV53  4.99K_0402_1%  [R_0402]  35.36 101.45 90 top
RV54  40.2_0402_1%  [R_0402]  39.05 101.32 90 bottom
RV55  40.2_0402_1%  [R_0402]  38.16 101.32 90 bottom
RV56  243_0402_1%  [R_0402]  35.36 101.32 90 bottom
RV57  243_0402_1%  [R_0402]  27.41 91.62 0 top
RV58  4.7K_0402_5%  [R_0402]  59.49 105.74 0 bottom
RV59  10K_0402_5%  [R_0402]  69.42 77.19 90 top
RV60  0_0603_5%  [R_0603]  71.28 88.7 270 top
RV71  10K_0402_5%  [R_0402]  83.75 89.29 270 bottom
